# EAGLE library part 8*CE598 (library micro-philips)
8bit 8051 Microcontroller, CAN 2.0A Without ROM P80CE598FFB/P80CE598FHB With ROM P83CE598FFB/P83CE598FHB
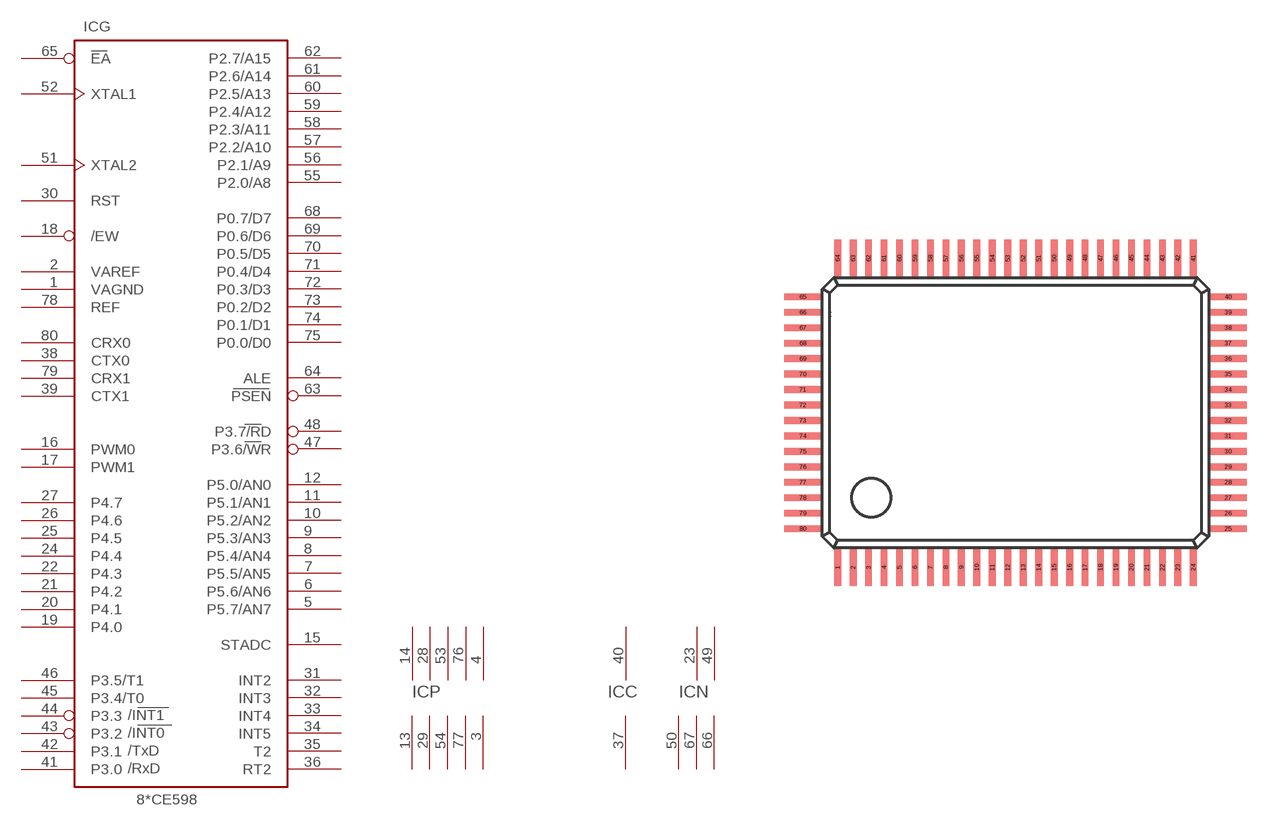
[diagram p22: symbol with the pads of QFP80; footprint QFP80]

Designator prefix IC; gates G=8XC598 P=PWR5 C=PWRC N=NC5

## 80CE598FP (OC_FARNELL: unknown; OC_NEWARK: unknown), 83CE598FP (OC_FARNELL: unknown; OC_NEWARK: unknown)  [QFP80]
1  G:VAGND
2  G:VAREF
3  P:GND  pwr
4  P:VCC  pwr
5  G:P5.7/AN7
6  G:P5.6/AN6
7  G:P5.5/AN5
8  G:P5.4/AN4
9  G:P5.3/AN3
10  G:P5.2/AN2
11  G:P5.1/AN1
12  G:P5.0/AN0
13  P:GND  pwr
14  P:VCC  pwr
15  G:STADC
16  G:PWM0
17  G:PWM1
18  G:/EW
19  G:P4.0
20  G:P4.1
21  G:P4.2
22  G:P4.3
23  N:NC  nc
24  G:P4.4
25  G:P4.5
26  G:P4.6
27  G:P4.7
28  P:VCC  pwr
29  P:GND  pwr
30  G:RST  in
31  G:INT2
32  G:INT3
33  G:INT4
34  G:INT5
35  G:T2
36  G:RT2
37  C:CGND  pwr
38  G:CTX0
39  G:CTX1
40  C:CVCC  pwr
41  G:P3.0
42  G:P3.1
43  G:P3.2
44  G:P3.3
45  G:P3.4/T0
46  G:P3.5/T1
47  G:P3.6/WR
48  G:P3.7/RD
49  N:NC  nc
50  N:NC  nc
51  G:XTAL2  in
52  G:XTAL1  in
53  P:VCC  pwr
54  P:GND  pwr
55  G:P2.0/A8
56  G:P2.1/A9
57  G:P2.2/A10
58  G:P2.3/A11
59  G:P2.4/A12
60  G:P2.5/A13
61  G:P2.6/A14
62  G:P2.7/A15
63  G:PSEN  out
64  G:ALE  out
65  G:EA  in
66  N:NC  nc
67  N:NC  nc
68  G:P0.7/D7
69  G:P0.6/D6
70  G:P0.5/D5
71  G:P0.4/D4
72  G:P0.3/D3
73  G:P0.2/D2
74  G:P0.1/D1
75  G:P0.0/D0
76  P:VCC  pwr
77  P:GND  pwr
78  G:REF
79  G:CRX1
80  G:CRX0

## Footprint QFP80 (pad centres in mm)
Quad Flat Pack
smd 0.35 x 1.9: 1 -8.8,-7.53; 2 -8,-7.53; 3 -7.2,-7.53; 4 -6.4,-7.53; 5 -5.6,-7.53; 6 -4.8,-7.53; 7 -4,-7.53; 8 -3.2,-7.53; 9 -2.4,-7.53; 10 -1.6,-7.53; 11 -0.8,-7.53; 12 0,-7.53; 13 0.8,-7.53; 14 1.6,-7.53; 15 2.4,-7.53; 16 3.2,-7.53; 17 4,-7.53; 18 4.8,-7.53; 19 5.6,-7.53; 20 6.4,-7.53; 21 7.2,-7.53; 22 8,-7.53; 23 8.8,-7.53; 24 9.6,-7.53; 41 9.6,8.47; 42 8.8,8.47; 43 8,8.47; 44 7.2,8.47; 45 6.4,8.47; 46 5.6,8.47; 47 4.8,8.47; 48 4,8.47; 49 3.2,8.47; 50 2.4,8.47; 51 1.6,8.47; 52 0.8,8.47; 53 0,8.47; 54 -0.8,8.47; 55 -1.6,8.47; 56 -2.4,8.47; 57 -3.2,8.47; 58 -4,8.47; 59 -4.8,8.47; 60 -5.6,8.47; 61 -6.4,8.47; 62 -7.2,8.47; 63 -8,8.47; 64 -8.8,8.47
smd 1.9 x 0.35: 25 11.4,-5.53; 26 11.4,-4.73; 27 11.4,-3.93; 28 11.4,-3.13; 29 11.4,-2.33; 30 11.4,-1.53; 31 11.4,-0.73; 32 11.4,0.07; 33 11.4,0.87; 34 11.4,1.67; 35 11.4,2.47; 36 11.4,3.27; 37 11.4,4.07; 38 11.4,4.87; 39 11.4,5.67; 40 11.4,6.47; 65 -10.6,6.47; 66 -10.6,5.67; 67 -10.6,4.87; 68 -10.6,4.07; 69 -10.6,3.27; 70 -10.6,2.47; 71 -10.6,1.67; 72 -10.6,0.87; 73 -10.6,0.07; 74 -10.6,-0.73; 75 -10.6,-1.53; 76 -10.6,-2.33; 77 -10.6,-3.13; 78 -10.6,-3.93; 79 -10.6,-4.73; 80 -10.6,-5.53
